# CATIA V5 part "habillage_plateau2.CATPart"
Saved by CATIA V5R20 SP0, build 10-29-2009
Part number: habillage_plateau2
Bounding box of the stored display mesh (mm): x -5 to 100, y 40 to 400, z -59.902 to 105
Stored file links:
  C:\Users\Noëllie\Documents\IFMA\2A\S3\IAO\Projet Artobolevski\Catia\habillage_plateau2.CATPart
  C:\Users\Noëllie\Documents\IFMA\2A\S3\IAO\Projet Artobolevski\Catia\assemblage_balance.CATProduct
  C:\Users\Noëllie\Documents\IFMA\2A\S3\IAO\Projet Artobolevski\Catia\habillage_plateau1.CATPart
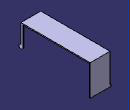
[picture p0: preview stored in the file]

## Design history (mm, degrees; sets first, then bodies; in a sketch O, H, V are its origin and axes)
Set1
  Plane1 "Plan_horizontal_plateau2": linked copy from another document
  Point1: linked copy from another document
  Point2 "B1d": linked copy from another document
  Point3 "pp_22": linked copy from another document
  Point4: linked copy from another document
  Plane2 "plan_vertical_plateau2": linked copy from another document
  Point5 "pp_21": linked copy from another document
  Point6 "pp_23": linked copy from another document
  Plane3 "plan_plateau2_bielle": linked copy from another document
  Point7 "C2": linked copy from another document
  Plane4 "plan_plateau2_support1": linked copy from another document
Body1 (main body)
  Sketch1 on Plane1, origin (0, 0, 100), H (1, 0, 0), V (0, 1, 0)
    point P1 (0, 400)
    line L1 (0, 400) -> (100, 400)
    line L2 (100, 400) -> (100, 50)
    line L3 (100, 50) -> (0, 50)
    line L4 (0, 50) -> (0, 400)
    point P2 (100, 400)
    point P3 (100, 50)
    point P4 (0, 50)
    reference projected point E1 (0, 50) from Point1
    reference projected point E2 (100, 50) from Point2
    reference projected point E3 (0, 400) from Point3
    reference projected point E4 (100, 400) from Point4
    horizontal: L1 H, L3 H
    vertical: L2 V, L4 V
    coincidence: P4 E1, P3 E2, P1 E3, E4 P2
  Pad1: profile Sketch1, direction (0, 0, 1), length 5
  Sketch2 on Plane2, origin (0, 400, 0), H (-1, 0, 0), V (0, 0, 1)
    point P1 (-100, 100)
    line L1 (-100, 100) -> (0, 100)
    line L2 (0, 100) -> (0, -50)
    line L3 (0, -50) -> (-100, -50)
    line L4 (-100, -50) -> (-100, 100)
    point P2 (0, 100)
    point P3 (0, -50)
    reference projected point E1 (-100, 100) from Point5
    reference projected point E2 (0, 100) from Point3
    reference projected point E3 (0, -50) from Point6
    horizontal: L1 H, L3 H
    vertical: L2 V, L4 V
    coincidence: P1 E1, P2 E2, P3 E3
  Pad2: profile Sketch2, direction (0, 1, 0), length 0, opposite side length 5
  Sketch3 on Plane3, origin (0, 0, 0), H (0, 1, 0), V (0, 0, 1)
    line L1 (400, -40) -> (350, -40)
    arc A1 centre (350, -50) radius 10 from (350, -40) to (358.3333, -55.5277) ccw
    point P4 (350, -50)
    reference projected point E1 (350, -50) from Point7
    line L2 (400, -40) -> (400, -50)
    point P5 (400, -50)
    line L3 (400, -50) -> (362, -50)
    line L4 (362, -50) -> (358.3333, -55.5277)
    reference projected point E2 (400, -50) from Point6
    length L3 = 38
    length L2 = 10
    horizontal: L1 H, L3 H
    coincidence: P4 E1, P5 E2
    vertical: L2 V
    tangency: A1 L4, L1 A1
  Pad3: profile Sketch3, direction (1, 0, 0), length 0, opposite side length 5
  Sketch4 on Plane4, origin (100, 0, 0), H (0, 1, 0), V (0, 0, 1)
    line L1 (60, 100) -> (60, 0)
    point P3 (50, 100)
    line L2 (50, 100) -> (60, 100)
    arc A1 centre (50, 0) radius 10 from (50, 10) to (60, 0) ccw
    point P5 (50, 0)
    reference projected point E1 (50, 0) from Point2
    reference projected point E2 (50, 100) from Point5
    line L3 (50, 10) -> (50, 100)
    length L2 = 10
    vertical: L1 V, L3 V
    horizontal: L2 H
    tangency: L1 A1
    coincidence: E1 P5, E2 P3
  Pad4: profile Sketch4, direction (1, 0, 0), length 0, opposite side length 5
